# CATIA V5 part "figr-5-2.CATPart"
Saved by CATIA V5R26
Part number: Part1
Bounding box of the stored display mesh (mm): x -23 to 23, y -104 to 104, z 0 to 68
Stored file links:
  D:\_Deepak\CATIA\CATIA V5-6R2016_Deepak\Resources\Part files\Partfiles\c05_catia_v5_6r2016_prt\figr-5-2.CATPart
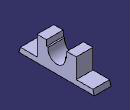
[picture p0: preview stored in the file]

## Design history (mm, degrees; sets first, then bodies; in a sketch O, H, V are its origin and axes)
Sketch1 on yz-plane, origin (0, 0, 0), H (0, 1, 0), V (0, 0, 1)
  line L1 (0, 0) -> (104, 0)
  point P1 (104, 0)
  line L2 (104, 0) -> (100, 14)
  point P2 (100, 14)
  line L3 (100, 14) -> (54, 14)
  point P3 (54, 14)
  line L4 (54, 14) -> (54, 68)
  point P4 (54, 68)
  line L5 (54, 68) -> (28, 68)
  point P5 (28, 68)
  line L6 (28, 68) -> (28, 52)
  point P6 (28, 52)
  line L7 (28, 52) -> (23.6643, 52)
  axis line L8 (0, 0) -> (0, 150)
  point P8 (0, 0)
  construction line L9 through (0, 0) direction (-1, 0)
  construction line L10 through (0, 0) direction (0, 1)
  point P13 (-104, 0)
  point P14 (-100, 14)
  point P15 (-54, 14)
  point P16 (-54, 68)
  point P17 (-28, 68)
  point P18 (-28, 52)
  line L11 (0, 0) -> (-104, 0)
  line L12 (-104, 0) -> (-100, 14)
  line L13 (-100, 14) -> (-54, 14)
  line L14 (-54, 14) -> (-54, 68)
  line L15 (-54, 68) -> (-28, 68)
  line L16 (-28, 68) -> (-28, 52)
  line L17 (-28, 52) -> (-23.6643, 52)
  arc A1 centre (0, 48) radius 24 from (-23.6643, 52) to (23.6643, 52) ccw
  point P19 (0, 48)
  point P20 (13.2665, 68)
  distance P1 P13 = 208
  length L2 V = 14
  length L2 H = 4
  distance L4 L14 = 108
  distance L16 L6 = 56
  distance L1 L5 = 68
  length L6 = 16
  distance P19 L7 = 4
  radius A1 = 24
  horizontal: L1 H, L3 H, L5 H, L7 H
  vertical: L4 V, L6 V, L8 V
  symmetry: O P8 L8, H L9 L8, V L10 L8, P1 P13 L8, P2 P14 L8, P3 P15 L8, P4 P16 L8, P5 P17 L8, P6 P18 L8, L1 L11 L8, L2 L12 L8, L3 L13 L8, L4 L14 L8, L5 L15 L8, L6 L16 L8, L7 L17 L8
  coincidence: P19 L8, A1 P20, P20 L5, O P8
Pad1: profile Sketch1, direction (1, 0, 0), length 23, mirrored extent
Body1 (main body)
